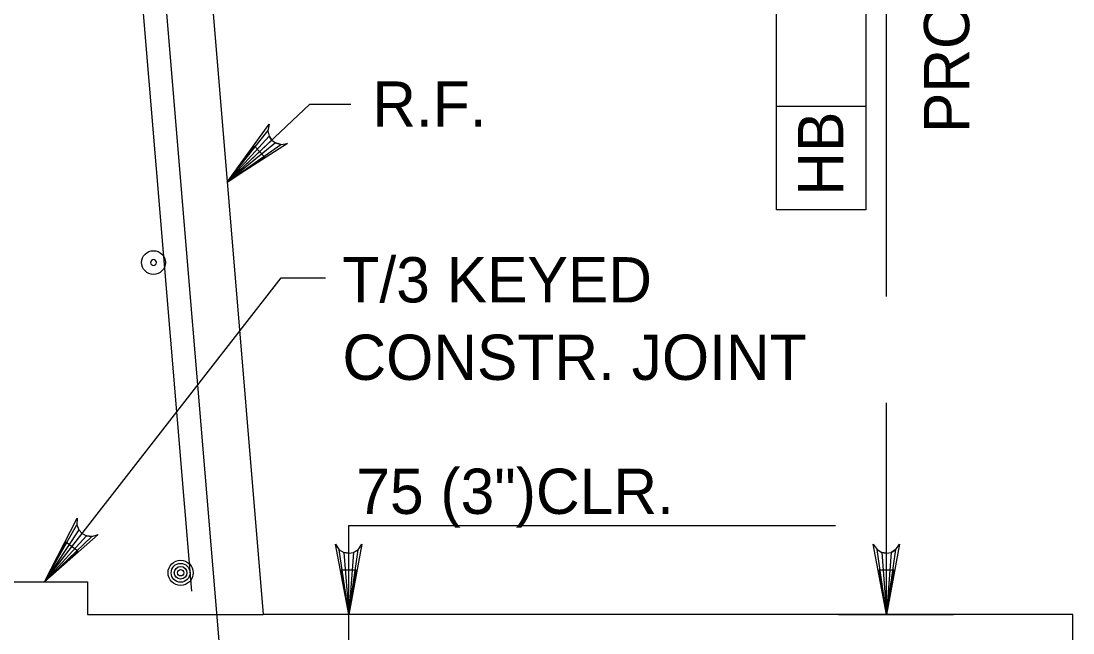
# Model space of a CAD drawing. Extents: x 634540 to 640306, y 296059 to 300275.
# Drawn here: x 639117.1 to 639186.8, y 297624.1 to 297664.6 of the extents above; entities that cross this region are included whole.
import ezdxf

# ---------------------------------------------------------------- set-up
doc = ezdxf.new("R2010")
doc.units = 0
for name, color, linetype in [('3', 7, 'Continuous'), ('4', 7, 'Continuous'), ('5', 7, 'Continuous'), ('6', 7, 'Continuous'), ('7', 7, 'Continuous'), ('9', 7, 'Continuous')]:
    doc.layers.add(name, color=color, linetype=linetype)

# ---------------------------------------------------------------- blocks, each defined once
blk = doc.blocks.new('B')
at = {"layer": '3'}
blk.add_circle((0, 0), 0.16, dxfattribs=at)
for start, end in [(0, 180), (180, 0)]:
    blk.add_arc((0, 0), 0.0391, start, end, dxfattribs=at)

msp = doc.modelspace()

# ---------------------------------------------------------------- linework, layer by layer
at = {"layer": '3'}
for p, q in [((639174.457, 297646.357), (639174.457, 297696.002)), ((639167.175, 297658.945), (639167.175, 297687.4)), ((639173.079, 297687.4), (639173.079, 297652.099)), ((639130.777, 297653.934), (639136.244, 297659.095)), ((639136.244, 297659.095), (639138.978, 297659.095)), ((639167.175, 297652.099), (639167.175, 297658.945)), ((639173.079, 297658.945), (639167.175, 297658.945)), ((639173.079, 297652.099), (639167.175, 297652.099)), ((639118.673, 297627.448), (639134.344, 297647.603)), ((639134.344, 297647.603), (639137.296, 297647.603)), ((639174.457, 297625.286), (639174.457, 297639.31)), ((639138.828, 297631.183), (639171.077, 297631.183)), ((639171.283, 297625.285), (639178.886, 297625.285))]:
    msp.add_line(p, q, dxfattribs=at)
for points in [[(639130.777, 297653.934), (639133.567, 297657.77), (639133.475, 297657.341), (639133.557, 297656.987), (639133.732, 297656.724), (639133.986, 297656.532), (639134.334, 297656.432), (639134.767, 297656.499), (639130.777, 297653.934), (639134.334, 297656.432), (639133.986, 297656.532), (639130.777, 297653.934), (639133.732, 297656.724), (639133.557, 297656.987), (639130.777, 297653.934), (639133.475, 297657.341)], [(639118.673, 297627.448), (639120.844, 297631.663), (639120.819, 297631.227), (639120.952, 297630.89), (639121.167, 297630.654), (639121.446, 297630.506), (639121.806, 297630.46), (639122.223, 297630.592), (639118.673, 297627.448), (639121.806, 297630.46), (639121.446, 297630.506), (639118.673, 297627.448), (639121.167, 297630.654), (639120.952, 297630.89), (639118.673, 297627.448), (639120.819, 297631.227)], [(639138.828, 297625.277), (639137.955, 297629.937), (639138.203, 297629.579), (639138.515, 297629.394), (639138.828, 297629.339), (639139.14, 297629.394), (639139.453, 297629.579), (639139.701, 297629.937), (639138.828, 297625.277), (639139.453, 297629.579), (639139.14, 297629.394), (639138.828, 297625.277), (639138.828, 297629.339), (639138.515, 297629.394), (639138.828, 297625.277), (639138.203, 297629.579)], [(639174.456, 297625.285), (639173.583, 297629.946), (639173.831, 297629.587), (639174.144, 297629.402), (639174.456, 297629.348), (639174.769, 297629.402), (639175.081, 297629.587), (639175.329, 297629.946), (639174.456, 297625.285), (639175.081, 297629.587), (639174.769, 297629.402), (639174.456, 297625.285), (639174.456, 297629.348), (639174.144, 297629.402), (639174.456, 297625.285), (639173.831, 297629.587)]]:
    msp.add_lwpolyline(points, dxfattribs=at)
for points in [[(639133.263, 297655.601), (639132.586, 297656.318), (639130.777, 297653.932)], [(639120.873, 297629.477), (639120.096, 297630.081), (639118.673, 297627.448)], [(639173.965, 297628.237), (639174.948, 297628.237), (639174.456, 297625.285)]]:
    msp.add_lwpolyline(points, close=True, dxfattribs=at)
at = {"layer": '4'}
msp.add_line((639138.828, 297622.21), (639138.828, 297631.183), dxfattribs=at)
msp.add_lwpolyline([(639139.319, 297628.231), (639138.336, 297628.231), (639138.828, 297625.277)], close=True, dxfattribs=at)
at = {"layer": '5'}
for p, q in [((639124.856, 297669.431), (639128.406, 297626.823)), ((639126.371, 297669.773), (639131.529, 297607.88))]:
    msp.add_line(p, q, dxfattribs=at)
for radius in [0.833, 0.625, 0.417, 0.208]:
    msp.add_circle((639127.69, 297628.047), radius, dxfattribs=at)
at = {"layer": '6'}
msp.add_lwpolyline([(639103.291, 297625.285), (639114.322, 297625.285), (639114.322, 297627.448), (639121.514, 297627.448), (639121.514, 297625.285), (639133.165, 297625.285)], dxfattribs=at)
at = {"layer": '7'}
for p, q in [((639182.815, 297625.277), (639182.815, 297625.277)), ((639186.574, 297625.277), (639186.574, 297625.277))]:
    msp.add_line(p, q, dxfattribs=at)
at = {"layer": '9'}
for p, q in [((639121.746, 297762.308), (639133.165, 297625.285)), ((639186.811, 297625.285), (639133.165, 297625.285)), ((639186.811, 297600.678), (639186.811, 297625.285))]:
    msp.add_line(p, q, dxfattribs=at)

# ---------------------------------------------------------------- block references
at = {"layer": '3', "xscale": 4.921475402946, "yscale": 4.921475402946, "rotation": 90}
msp.add_blockref('B', (639125.894, 297648.607), dxfattribs=at)

# ---------------------------------------------------------------- texts
at = {"layer": '3'}
for s, p in [('PROJECTION', (639179.94, 297657.193)), ('HB', (639171.594, 297653.039))]:
    msp.add_text(s, height=3.0001, rotation=90, dxfattribs=at).set_placement(p)
for s, height, p in [('R.F.', 3.0001, (639140.386, 297657.61)), ('T/3 KEYED', 3.0001, (639138.409, 297645.965)), ('CONSTR. JOINT', 3.00014, (639138.409, 297640.83)), ('75 (3")CLR.', 3.00014, (639139.328, 297631.948))]:
    msp.add_text(s, height=height, dxfattribs=at).set_placement(p)

doc.saveas('drawing.dxf')
